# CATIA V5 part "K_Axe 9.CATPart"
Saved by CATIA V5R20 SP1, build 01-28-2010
Part number: Corps 2
Publications: "Raton 15 2"
Bounding box of the stored display mesh (mm): x -285.979 to 361, y -350 to 350, z -50 to 120.976
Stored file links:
  G:\Khaled_CFAO_2011\SIL\SIL_GR1\gperrin\Khaled\CAD_CATIA\Khaled\K_Axe 9.CATPart
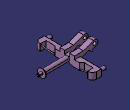
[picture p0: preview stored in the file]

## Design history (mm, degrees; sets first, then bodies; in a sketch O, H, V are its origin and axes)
Parameters
  `Raton 15 2` = 20 mm
Set1
  TriDim1
  Extract1: ExtractElem face of DatumSurface1
  DatumSurface1
  Fill1: Boundary edge of DatumSurface1
  Fill2: Boundary edge of DatumSurface1
  Healing1: BodyToHeal (Extract1; Fill1; Fill2), TangencyAngle 0.5, SharpnessAngle 0.5
  CloseSurface1: CloseElement Healing1
  Add1: tool TriDim1
  Extrude1: Lim1 0, Lim2 0, Direction face of CloseSurface1, Element1 face of CloseSurface1, FirstUpto face of TriDim1
  Add2: tool Extrude1
  Plane1: type OffsetPt, RefPlane face of TriDim1, RefPoint vertex [face of TriDim1 | face of TriDim1 | face of TriDim1 | face of TriDim1 | face of TriDim1]
  Split1: ToCut Add2, Cutting Plane1
  Symmetry1: Reference Plane1, ToTransfor Split1
  Add3: tool Symmetry1
  TriDim2
Body1 (main body)
  Sketch1 on xy-plane, origin (0, 0, 0), H (1, 0, 0), V (0, 1, 0)
    point P1 (0, 60.1601)
    line L1 (310, 50) -> (313, 50)
    line L2 (313, 50) -> (313, 16)
    line L3 (320, 0) -> (0, 0)
    line L4 (0, 0) -> (0, 30)
    point P3 (320, 0)
    point P5 (310, 50)
    arc A1 centre (290, 50) radius 20 from (290, 30) to (310, 50) ccw
    point P6 (290, 50)
    line L5 (290, 30) -> (0, 30)
    point P7 (290, 30)
    point P9 (290, 30)
    point P10 (310, 50)
    axis line L6 (-243, 0) -> (331, 0)
    point P11 (-243, 0)
    line L7 (361, 12.2297) -> (361, 0)
    line L8 (361, 0) -> (320, 0)
    point P14 (361, 0)
    line L9 (313, 16) -> (351, 16)
    line L10 (355, 16) -> (355, 12)
    line L11 (355, 12) -> (351, 12)
    line L12 (351, 12) -> (351, 16)
    line L13 (355, 16) -> (357.2297, 16)
    line L14 (357.2297, 16) -> (361, 12.2297)
    length L3 = 320
    length L5 = 290
    length L4 = 30
    distance L1 L3 = 50
    distance L2 L7 = 48
    length L11 = 4
    length L10 = 4
    length L9 = 38
    angle L13 L14 = 45
    length L14 = 5.332
    distance L9 L8 = 16
    horizontal: L1 H, L3 H, L6 H, L8 H, L9 H, L11 H, L13 H
    vertical: L2 V, L4 V, L7 V, L10 V, L12 V
    coincidence: P3 H, P6 L1, A1 P5, P7 A1, L1 P10, L5 P9, P11 L3, P5 P10, P7 P9, P14 L3, L9 L13
    tangency: L5 A1
  Shaft1: profile Sketch1, axis Sketch1.L6, angle 360
  Sketch2 on face of Shaft1 from Sketch1.L4, origin (0, 0, 0), H (0, -1, 0), V (0, 0, 1)
    line L1 (350, 0) -> (350, 30)
    line L2 (350, 30) -> (0, 30)
    point P1 (350, 0)
    point P2 (350, 30)
    point P3 (0, 30)
    construction line L3 (-11, 0) -> (209, 0)
    point P4 (-11, 0)
    axis line L4 (0, 0) -> (0, 131)
    point P7 (350, -30)
    point P8 (350, 0)
    line L5 (350, 0) -> (350, -30)
    point P9 (0, -30)
    line L6 (350, -30) -> (0, -30)
    point P10 (0, 30)
    point P11 (-350, 30)
    line L7 (-350, 30) -> (0, 30)
    point P12 (-350, 0)
    line L8 (-350, 0) -> (-350, 30)
    point P13 (-350, -30)
    point P14 (-350, 0)
    line L9 (-350, 0) -> (-350, -30)
    point P15 (0, -30)
    line L10 (-16, -30) -> (0, -30)
    line L11 (-16, -30) -> (-70.9495, -50)
    point P16 (-16, -30)
    line L12 (-70.9495, -50) -> (-295.0505, -50)
    line L13 (-295.0505, -50) -> (-350, -30)
    length L1 = 30
    length L2 = 350
    angle L11 L10 = 20
    angle L13 L10 = 20
    distance L12 L10 = 20
    distance P9 P16 = 16
    horizontal: L2 H, L3 H, L12 H
    vertical: L1 V, L4 V
    coincidence: P4 H, P1 P8, P3 P10, P9 P15, P12 P14
    symmetry: P2 P7 L3, P1 P8 L3, L1 L5 L3, P3 P9 L3, L2 L6 L3, P3 P10 L4, P2 P11 L4, L2 L7 L4, P1 P12 L4, L1 L8 L4, P7 P13 L4, P8 P14 L4, L5 L9 L4, P9 P15 L4, L6 L10 L4
  Pad1: profile Sketch2, direction (-1, 0, 0), length 70
  Sketch3 on zx-plane, origin (0, 0, 0), H (-1, 0, 0), V (0, 0, 1)
    line L1 (0, 0) -> (0, 29.1815)
    line L2 (0, 0) -> (0, -30)
    line L3 (0, -30) -> (156.6907, 38.9833)
    arc A1 centre (247, 18) radius 25 from (247, 43) to (226.7597, 3.3259) ccw
    point P4 (247, 18)
    arc A2 centre (169.8982, 8.9833) radius 32.7786 from (200.1157, 21.6853) to (156.6907, 38.9833) ccw
    point P6 (270.0968, 27.5676)
    arc A3 centre (247, 82) radius 39 from (247, 43) to (233.0538, 118.4212) ccw
    point P7 (247, 82)
    line L4 (109.211, 71) -> (233.0538, 118.4212)
    circle A4 centre (247, 82) radius 19
    arc A5 centre (231.0479, 38.0622) radius 35 from (200.1157, 21.6853) to (226.7597, 3.3259) ccw
    point P13 (0, 71)
    line L5 (0, 71) -> (0, 29.1815)
    point P14 (0, 29.1815)
    line L6 (0, 71) -> (109.211, 71)
    length L2 = 30
    radius A1 = 25
    distance P4 P7 = 64
    radius A4 = 19
    radius A5 = 35
    angle L3 L1 = 66.2384
    distance L6 H = 71
    angle L4 L6 = 159.0474
    vertical: L1 V, L2 V, L5 V
    tangency: A2 L3, A3 A1, L4 A3
    coincidence: P6 A1, P13 V, P14 L4
    horizontal: L6 H
  Pad2: profile Sketch3, direction (0, 1, 0), length 90, mirrored extent
  Sketch4 on face of Pad2 from Sketch3.L4, origin (9.6947, 0, 25.4693), H (0, 1, 0), V (-0.9339, 0, 0.3576)
    line L1 (-30, 80) -> (30, 80)
    line L2 (30, 80) -> (30, 313)
    line L3 (30, 313) -> (-30, 313)
    line L4 (-30, 313) -> (-30, 80)
    reference projected line E1 (90, 259.9363) -> (90, 127.3249) from edge [face of Pad2 from Sketch3.L4 | end face of Pad2]
    distance E1 L2 = 60
    distance L1 H = 80
    length L3 = 60
    horizontal: L1 H, L3 H
    vertical: L2 V, L4 V
  Pocket1: profile Sketch4, direction (-0.3576, 0, -0.9339), through (limit type 3)
  Sketch5 on yz-plane, origin (0, 0, 0), H (0, 1, 0), V (0, 0, 1)
    line L1 (-30, 78) -> (30, 78)
    line L2 (30, 78) -> (30, 30)
    line L3 (30, 30) -> (-30, 30)
    line L4 (-30, 30) -> (-30, 78)
    length L1 = 60
    distance L3 H = 30
    distance V L2 = 30
    horizontal: L1 H, L3 H
    vertical: L2 V, L4 V
  Pocket2: profile Sketch5, direction (-1, 0, 0), through (limit type 3)
  Mirror1: of the body so far, about zx-plane
  Sketch6 on face of Mirror1, origin (-70, 0, 0), H (0, -1, 0), V (0, 0, 1)
    circle A1 centre (330, 0) radius 20
    point P1 (330, 0)
    radius A1 = 20 {= `Raton 15 2`}
    distance P1 V = 330
    coincidence: P1 H
  Pad3: profile Sketch6, direction (-1, 0, 0), length 60
  Sketch7 on face of Mirror1, origin (0, 0, 30), H (1, 0, 0), V (0, 1, 0)
    line L1 (0, -150) -> (-30, -180)
    point P1 (0, -150)
    line L2 (-30, -180) -> (-30, -310)
    line L3 (-30, -310) -> (-53.094, -350)
    point P4 (-53.094, -350)
    line L4 (0, -350) -> (0, -150)
    point P5 (0, -350)
    reference projected line E1 (-109.211, -90) -> (0, -90) from edge [face of Mirror1 | face of Mirror1]
    reference projected line E2 (0, -350) -> (-70, -350) from edge [face of Mirror1 | face of Mirror1]
    line L5 (-53.094, -350) -> (0, -350)
    distance P1 E1 = 60
    angle L1 L4 = 45
    angle L3 L5 = 60
    distance L2 L4 = 30
    length L2 = 130
    coincidence: P1 V, P5 V, P4 E2
    vertical: L2 V, L4 V
    horizontal: L5 H
  Pocket3: profile Sketch7, direction (0, 0, -1), through (limit type 3)
  Mirror2: of Pad3, Sketch6, Pocket3, Sketch7, about zx-plane
  Sketch8 on face of Mirror1, origin (0, 0, 30), H (1, 0, 0), V (0, 1, 0)
    line L1 (-70, -290) -> (40, -290)
    line L2 (40, -290) -> (40, -296.7457)
    line L3 (-13.2543, -350) -> (-70, -350)
    line L4 (-70, -350) -> (-70, -290)
    reference projected line E1 (-70, -350) -> (-70, 0) from edge [face of Mirror1 | face of Pad1]
    reference intersected line E2 (0, -350) -> (-70, -350) from face of Mirror1
    arc A1 centre (-13.2543, -296.7457) radius 53.2543 from (40, -296.7457) to (-13.2543, -350) cw
    length L4 = 60
    length L1 = 110
    radius A1 = 53.2543
    horizontal: L1 H, L3 H
    vertical: L2 V, L4 V
    coincidence: L4 E1, L3 E2
    tangency: A1 L2, A1 L3
  Pad4: profile Sketch8, direction (0, 0, -1), length 80
  Mirror3: of Pad4, Sketch8, about zx-plane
